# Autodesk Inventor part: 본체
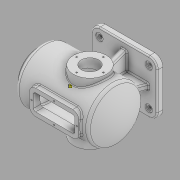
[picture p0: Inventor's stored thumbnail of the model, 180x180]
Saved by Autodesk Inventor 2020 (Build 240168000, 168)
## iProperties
Created: 2021-11
Part Number: 본체
Material: 일반
Document SubType Name: Modeling
Designer: Administrator
Density: 1 g/cm^3
Appearance: 기본값
Author: Administrator
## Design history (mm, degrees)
sketch "스케치1"
  geometry: L1 (80, -65)-(-80, -65); L2 (-80, -65)-(-80, 65); L3 (-80, 65)-(80, 65); L4 (80, 65)-(80, -65); L5 (80, -65)-(-80, 65); L6 (-80, -65)-(80, 65); 1 further point
  constraints: 12 end point, 2 midpoint, 2 parallel, 1 horizontal, 1 perpendicular
  dimensions: "d0" = 160 distance of L2.end L3.end; "d1" = 130 distance of L3.end L1.start
extrude "돌출1" new body sketch "스케치1" distance "d2" = 14; taper "d3" = 0 deg
sketch "스케치2"
  geometry: L1 (80, 0)-(-80, 0) reference; L2 (110, 114)-(-100, 114); L3 (110, 114)-(110, 161.5); L4 (110, 161.5)-(100, 161.5); L5 (100, 161.5)-(100, 179); L6 (100, 179)-(-75.993, 179); L7 (80, 0)-(80, 14) reference; L8 (110, 146.5)-(85, 146.5); L9 (85, 146.5)-(85, 169); L10 (85, 169)-(-71.239, 169); A1 r 100 centre (0, 114) between (-75.993, 179) and (-100, 114); A2 r 90 centre (0, 114) between (-71.239, 169) and (-90, 114); 2 further points
  constraints: 16 end point, 5 perpendicular, 4 point on circle, 3 point on line, 2 centre point, 2 horizontal, 1 vertical
  dimensions: "d13" = 30 distance between parallel lines of L7 L3; "d14" = 10 distance of L3.end L4.end; "d16" = 210 distance of L2.end L2.start; "d17" = 95 diameter of L4 L2; "d18" = 130 diameter of L6 L2; "d20" = 114 distance from line of L1 L2.end; "d21" = 100 radius of A1; "d22" = 10 radial gap between concentric circles of A1 A2; "d23" = 25 distance of L8.start L8.end; "d24" = 65 diameter of L8 L2; "d25" = 110 diameter of L10 L2
revolve "회전1" sketch "스케치2" stored, may be unused: angle "d26" = 90 deg
fillet "모깎기1" dims "d27" = 10
node "작업 평면1"
node "작업 평면6"
sketch "스케치9"
  geometry: L1 (60, 30)-(-60, 30); L2 (-60, 30)-(-60, -30); L3 (-60, -30)-(60, -30); L4 (60, -30)-(60, 30); L5 (110, -47.5)-(110, 47.5) reference; 2 further points
  constraints: 8 end point, 2 parallel, 1 horizontal, 1 horizontal alignment, 1 midpoint, 1 perpendicular
  dimensions: "d57" = 50 distance between parallel lines of L4 L5; "d58" = 120 distance of L1.start L1.end; "d59" = 60 distance of L1.end L2.end
extrude "돌출4" join sketch "스케치9" stored distance "d60" = 14; taper "d61" = 0 deg
sketch "스케치10"
  geometry: L1 (50, 20)-(-50, 20); L2 (-50, 20)-(-50, -20); L3 (-50, -20)-(50, -20); L4 (50, -20)-(50, 20); L5 (60, -30)-(60, 30) reference; L6 (-60, 30)-(-60, -30) reference; L7 (60, 30)-(-60, 30) reference; L8 (-60, -30)-(60, -30) reference; 1 further point
  constraints: 8 end point, 2 parallel, 1 horizontal, 1 perpendicular
  dimensions: "d62" = 10 distance between parallel lines of L4 L5; "d63" = 10 distance between parallel lines of L6 L2; "d64" = 10 distance between parallel lines of L1 L7; "d65" = 10 distance between parallel lines of L8 L3
extrude "돌출5" cut sketch "스케치10" stored distance "d66" = 14; taper "d67" = 0 deg
sketch "스케치11" dims "d68" = 80
  geometry: C1 r 47.5 at (0, 0) reference; C2 r 32.5 at (0, 0) reference; 3 further points
  constraints: 2 horizontal alignment, 1 coincident, 2 other
hole "구멍3" sketch "스케치11" at (40, 0) diameter "d69" = 3.45873; stored, may be unused: countersink angle "d73" = 90 deg, drill point angle "d75" = 118 deg; dims "d70" = 11, "d71" = 52, "d72" = 18, "d74" = 13
sketch "스케치12"
  geometry: L1 (7, -7)-(-7, -7); L2 (-7, -7)-(-7, 7); L3 (-7, 7)-(7, 7); L4 (7, 7)-(7, -7); L5 (7, -7)-(-7, 7); L6 (-7, -7)-(7, 7); 1 further point
  constraints: 12 end point, 2 midpoint, 2 parallel, 1 horizontal, 1 perpendicular
  dimensions: "d79" = 14 distance of L2.end L3.end; "d80" = 14 distance of L3.end L1.start
extrude "돌출6" join sketch "스케치12" stored distance "d81" = 14; taper "d82" = 0 deg
sketch "스케치13"
  geometry: L1 (80, 14)-(-80, 14) reference; L2 (60, 14)-(49.846, 41.898); 1 further point
  constraints: 2 end point, 1 point on line
  dimensions: "d83" = 60 horizontal distance of point (0, 0) L2.start; "d84" = 110 deg angle of L1 L2
feature "리브1" sketch "스케치13" dims "d85" = 1, "d86" = 14, "d87" = 0, "d88" = 0, "d89" = 1, "d90" = 1
sketch "스케치14"
  geometry: L1 (65, 14)-(-65, 14) reference; L2 (50, 14)-(37.587, 48.104); L3 (-65, 0)-(65, 0) reference; 1 further point
  constraints: 2 end point, 1 point on line
  dimensions: "d91" = 110 deg angle of L3 L2; "d92" = 50 horizontal distance of point (0, 0) L2.start
feature "리브2" sketch "스케치14" dims "d93" = 1, "d94" = 14, "d95" = 0, "d96" = 0, "d97" = 1, "d98" = 1
node "작업 평면7"
node "작업 평면8"
sketch "스케치15"
  geometry: L1 (110, 66.5)-(110, 161.5) reference; C1 r 40 at (-17, 114); 2 further points
  constraints: 1 centre point, 1 horizontal alignment, 1 midpoint
  dimensions: "d101" = 127 distance from line of C1.centre L1; "d102" = 80 diameter of C1
extrude "돌출7" join sketch "스케치15" stored distance "d103" = 14; taper "d104" = 0 deg
sketch "스케치16" dims "d105" = 65
  geometry: C1 r 40 at (0, 0) reference; 3 further points
  constraints: 2 vertical alignment, 1 coincident, 2 other
hole "구멍4" sketch "스케치16" at (0, 32.5) diameter "d106" = 3.45873; stored, may be unused: countersink angle "d110" = 90 deg, drill point angle "d112" = 118 deg; dims "d107" = 11, "d108" = 52, "d109" = 18, "d111" = 13
sketch "스케치17"
  geometry: 1 further point
sketch "스케치18"
  geometry: C1 r 40 at (0, 0) reference; C2 r 21 at (0, 0); 1 further point
  constraints: 1 centre point, 1 coincident
  dimensions: "d116" = 42 diameter of C2
extrude "돌출8" cut sketch "스케치18" extent not by distance; stored distance "d117" = 0; taper "d118" = 0 deg
sketch "스케치19"
  geometry: L1 (55, -25)-(-55, -25); L2 (-55, -25)-(-55, 25); L3 (-55, 25)-(55, 25); L4 (55, 25)-(55, -25); L5 (55, -25)-(-55, 25); L6 (-55, -25)-(55, 25); 7 further points
  constraints: 12 end point, 8 midpoint, 2 horizontal alignment, 2 parallel, 2 vertical alignment, 1 horizontal, 1 perpendicular
  dimensions: "d119" = 50 distance of point (0, -25) point (0, 25); "d120" = 110 distance of point (55, 0) point (-55, 0)
hole "구멍5" sketch "스케치19" at (0, 25), (-55, 0), (0, -25), (55, 0) diameter "d121" = 3.45873; stored, may be unused: countersink angle "d125" = 90 deg, drill point angle "d127" = 118 deg; dims "d122" = 11, "d123" = 52, "d124" = 18, "d126" = 13
fillet "모깎기2" dims "d128" = 20
sketch "스케치20"
  geometry: A1 r 20 centre (-60, -45) between (-80, -45) and (-60, -65) reference; A2 r 20 centre (60, -45) between (60, -65) and (80, -45) reference; A3 r 20 centre (-60, 45) between (-60, 65) and (-80, 45) reference; A4 r 20 centre (60, 45) between (80, 45) and (60, 65) reference; 5 further points
  constraints: 4 coincident
hole "구멍6" sketch "스케치20" at (-60, -45), (60, -45), (-60, 45), (60, 45) diameter "d129" = 9; stored, may be unused: countersink angle "d133" = 90 deg, drill point angle "d135" = 118 deg; dims "d130" = 11, "d131" = 18, "d132" = 2, "d134" = 2
fillet "모깎기3" dims "d136" = 3
fillet "모깎기4" dims "d137" = 3
fillet "모깎기5" dims "d138" = 3
fillet "모깎기6" dims "d139" = 15
fillet "모깎기7" dims "d140" = 3
fillet "모깎기8" dims "d141" = 5
fillet "모깎기9" dims "d142" = 5
fillet "모깎기10" dims "d143" = 10
sketch "스케치21"
  geometry: L1 (39.261, 8.002)-(80.739, 8.002); L2 (80.739, 8.002)-(80.739, 1.998); L3 (80.739, 1.998)-(39.261, 1.998); L4 (39.261, 1.998)-(39.261, 8.002); L5 (39.261, 8.002)-(80.739, 1.998); L6 (0, 0)-(120, 0) reference; 3 further points
  constraints: 2 end point, 2 midpoint, 1 vertical alignment, 2 other
  dimensions: "d144" = 5 distance of point (60, 0) point (60, 5)
feature "엠보싱1" sketch "스케치21" dims "d13" = 30, "d14" = 10, "d16" = 210, "d17" = 95, "d18" = 130, "d20" = 114, "d21" = 100, "d22" = 10, "d23" = 25, "d24" = 65, "d25" = 110, "d145" = 0.5, "d146" = 0
chamfer "모따기1" distance "d147" = 1; stored, may be unused: second distance "d148" = 2, angle "d149" = 45 deg
fillet "모깎기11" dims "d150" = 3
fillet "모깎기12" dims "d151" = 3
node "솔리드1"
mirror "미러1"
pattern_circular "원형 패턴2" dims angle "d77" = 360 deg
mirror "미러3"
mirror "미러4"
pattern_circular "원형 패턴3" dims angle "d114" = 360 deg
mirror "미러5"
node "작업 평면2"
node "투영된 루프2"
feature "A9D066F2-1C7D-4E18-AEED-F7BC21143FA4" dims "d129" = 9, "d130" = 11, "d131" = 18, "d132" = 2, "d133" = 90 deg, "d134" = 2, "d135" = 118 deg
other parameters: "d28" = 75, "d56" = -184, "d99" = -127, "d100" = -75
